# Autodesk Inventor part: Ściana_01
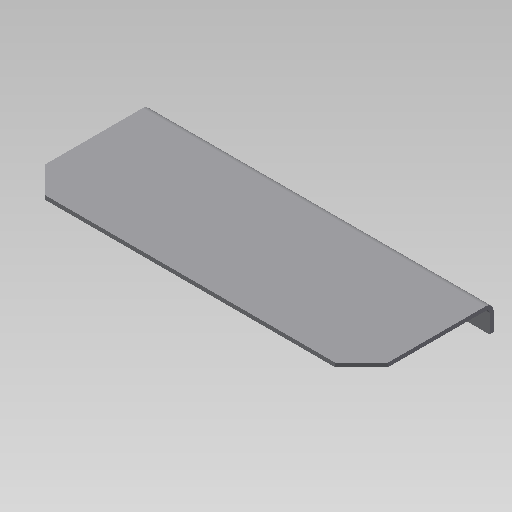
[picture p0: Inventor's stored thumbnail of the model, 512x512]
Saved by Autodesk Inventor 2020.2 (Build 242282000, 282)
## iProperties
Created: 2014-09
Part Number: Ściana_01
Material: Ogólny
Document SubType Name: Konstrukcja blachowa
Designer: F.Stasiak
Density: 1 g/cm^3
Sheet Metal Rule: Domyślny_mm
Appearance: Domyślna
Catalog Web Link: www.expertbooks.pl
Manager: www.cadconsulting.pl
Company: Fabian Stasiak CAD Consulting
Author: F.Stasiak
Subject: Zbiór ćwiczeń. Autodesk Inventor 2020. Kurs Professional
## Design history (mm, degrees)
node "Powierzchnia1"
  sketch "Szkic1"
    geometry: L1 (-53.625, 16.461)-(76.375, 16.461); L2 (76.375, 16.461)-(76.375, 26.461); L3 (76.375, 26.461)-(-53.625, 26.461); L4 (-53.625, 26.461)-(-53.625, 16.461); 1 further point
    constraints: 8 end point, 2 parallel, 1 horizontal, 1 perpendicular
    dimensions: "d0" = 130 distance of L3.end L2.end; "d1" = 10 distance of L2.end L1.end
node "Kołnierz1"
feature "Fazowanie narożnika1" dims "d13" = 10, "d14" = 6, angle "d15" = 45 deg
node "Bryła1"
feature "Płyta1" dims "d16" = 1.5 (= Grubość)
sketch "Szkic2"
  geometry: L1 (0, 50)-(-130, 50); L2 (-130, 50)-(-130, 0); 1 other entity
  constraints: 4 end point, 4 other
feature "Płyta2" dims "d3" = 1.5 (= SzerokośćGięciaPodcięcia), "d4" = 0.75 (= GłębokośćGięciaPodcięcia), "d5" = 3 (= MinimalnaPozostałość), "d6" = 1.5 (= PromieńGięcia), "d7" = 50, "d8" = 90 deg, "d9" = 1.5 (= PromieńGięcia), "d10" = 6 (= RozmiarPodcięciaNarożnika), "d11" = 1.5 (= Wielk_odstępu), "d12" = 1.5 (= Rozmiar_promienia_Jacobiego), "d16" = 1.5 (= Grubość), "OdstępPołączenia" = 0.01
feature "Gięcie1" dims "d3" = 1.5 (= SzerokośćGięciaPodcięcia), "d4" = 0.75 (= GłębokośćGięciaPodcięcia), "d5" = 3 (= MinimalnaPozostałość), "d6" = 1.5 (= PromieńGięcia), "d7" = 50, "d8" = 90 deg, "d9" = 1.5 (= PromieńGięcia), "d16" = 1.5 (= Grubość), "OdstępPołączenia" = 0.01
feature "Narożnik1" dims "d7" = 50, "d8" = 90 deg, "d10" = 6 (= RozmiarPodcięciaNarożnika), "d11" = 1.5 (= Wielk_odstępu), "d12" = 1.5 (= Rozmiar_promienia_Jacobiego)
other parameters: "Grubość" = 1.5 (derived), "WspółczynnikK" = 4.4, "PromieńGięcia" = 1.5 (= Grubość), "SzerokośćGięciaPodcięcia" = 1.5 (= Grubość), "GłębokośćGięciaPodcięcia" = 0.75 (= 0.5 x Grubość), "RozmiarPodcięciaNarożnika" = 6 (= 4 x Grubość), "MinimalnaPozostałość" = 3 (= 2 x Grubość), "PromieńPrzejścia" = 1.5 (= PromieńGięcia), "Rozmiar_promienia_Jacobiego" = 1.5 (= PromieńGięcia), "Wielk_odstępu" = 1.5 (= Grubość), "d2" = 1.5 (= PromieńGięcia)
